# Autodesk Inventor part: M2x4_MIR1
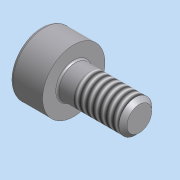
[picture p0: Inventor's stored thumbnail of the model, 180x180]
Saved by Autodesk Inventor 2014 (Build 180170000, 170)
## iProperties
Created: 2015-05
Part Number: M2x4_MIR1
Material: 일반
Vendor: CBT Solutions
Document SubType Name: 모델링
Designer: Administrator
Appearance: 기본값
Company: 한국ATC센터
Author: KYOUNG IL JANG
Comments: 파생
d0: 1.000 ul
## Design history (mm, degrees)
derived "M2x4.ipt" dims count "d0" = 1
feature "솔리드1::M2x4.ipt" dims count "d0" = 1
tag "피쳐 태그1"
node "솔리드1"
